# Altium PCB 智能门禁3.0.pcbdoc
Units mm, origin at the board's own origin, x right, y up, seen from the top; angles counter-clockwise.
Board outline 222.24 x 108 mm, 2 copper layers (Top Layer, Bottom Layer); 20 components, 31 nets, 107 pads, 14 vias.
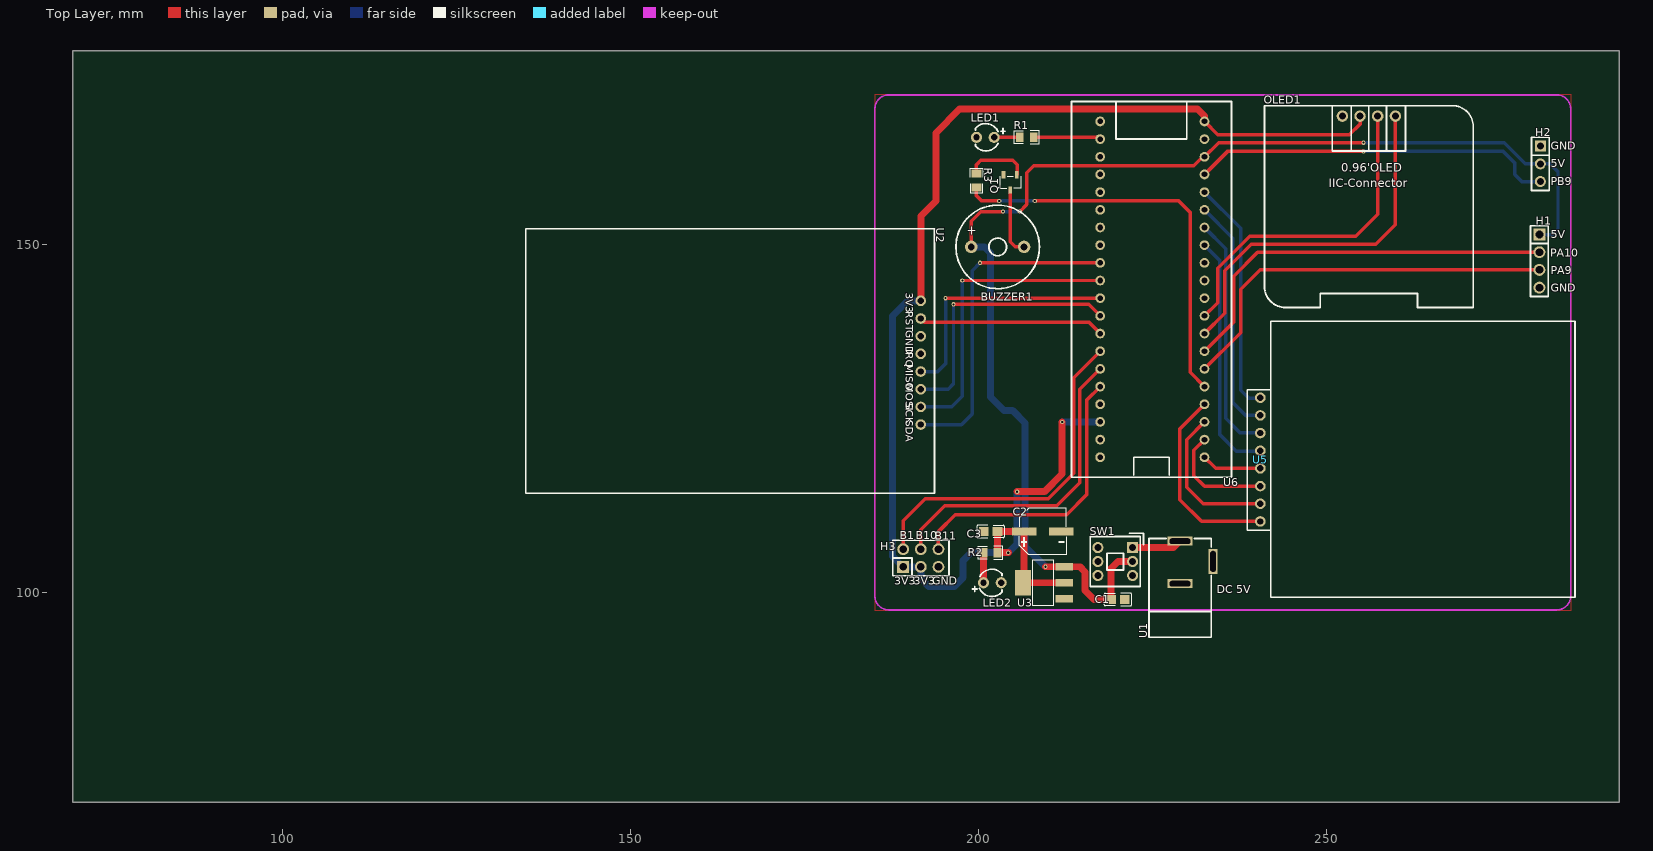
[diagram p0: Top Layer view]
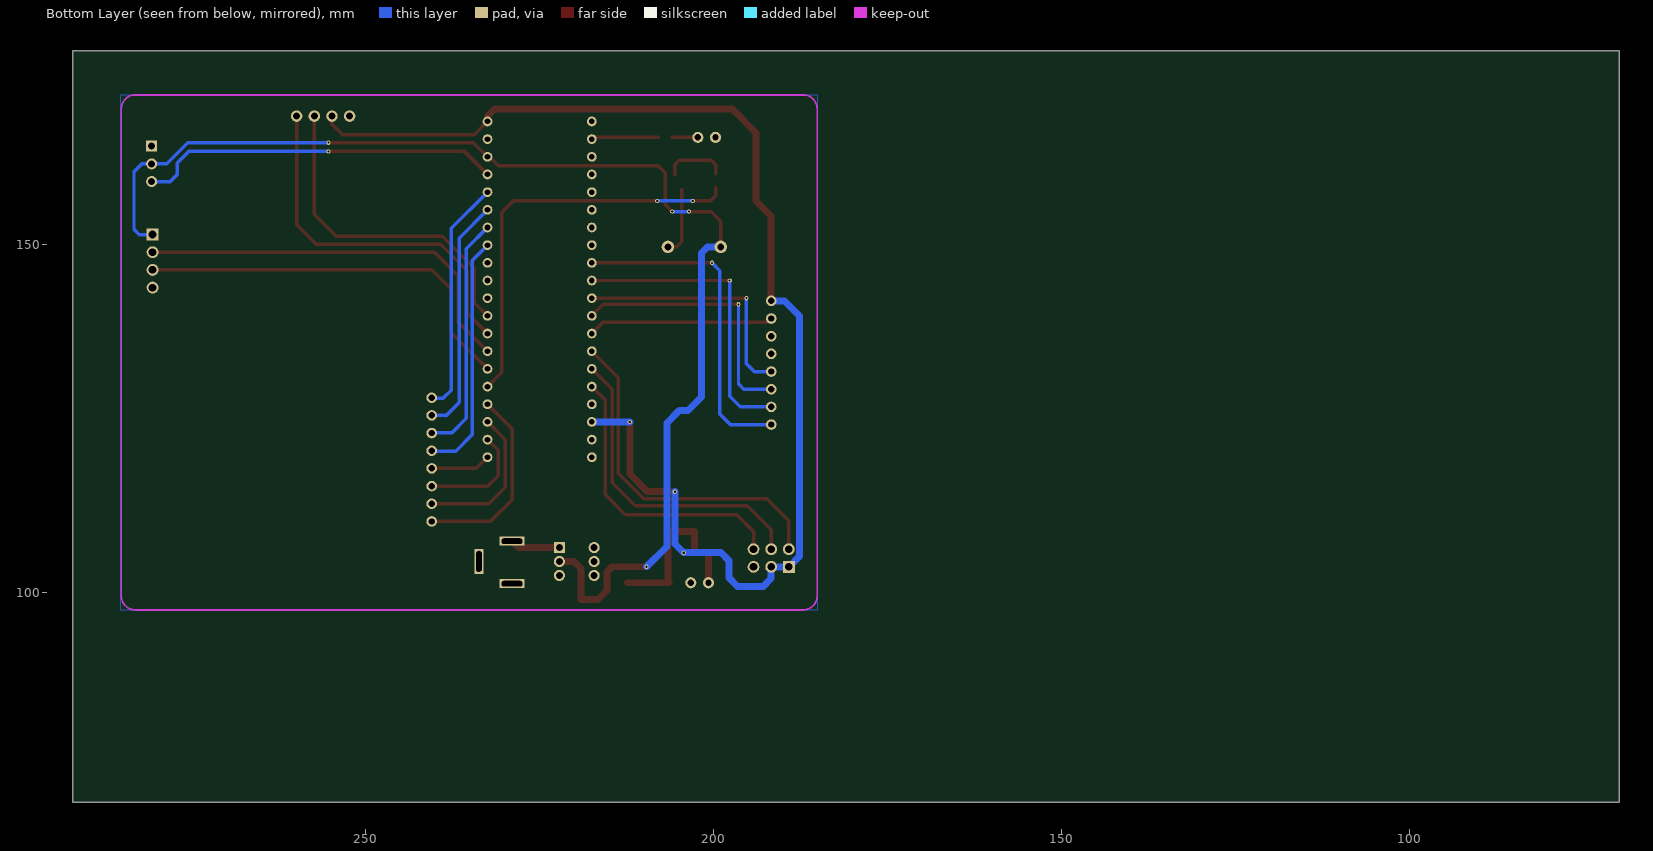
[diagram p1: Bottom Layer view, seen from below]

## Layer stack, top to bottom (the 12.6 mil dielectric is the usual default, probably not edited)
Top Layer: signal copper (thickness not stored)
Dielectric: dielectric 0.32, FR-4, Dk 4.8
Bottom Layer: signal copper (thickness not stored)

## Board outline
292.094,69.85 69.85,69.85 69.85,177.846 292.094,177.846

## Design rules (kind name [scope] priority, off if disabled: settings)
Clearance copperThickness1oz [All] p1: gap=0.178 ignorepadtopadclearanceinfootprint=FALSE except(0.102: Track-Track; 0.152: Track-SMDPad SMDPad-SMDPad Track-THPad SMDPad-THPad THPad-THPad Track-Via SMDPad-Via THPad-Via Via-Via Track-Fill SMDPad-Fill THPad-Fill Via-Fill Fill-Fill SMDPad-Region THPad-Region Via-Region Fill-Region Region-Region Track-Poly SMDPad-Poly THPad-Poly Via-Poly Fill-Poly Poly-Poly Track-Text SMDPad-Text THPad-Text Via-Text Fill-Text Region-Text Poly-Text Text-Text Track-Hole SMDPad-Hole THPad-Hole Via-Hole Fill-Hole Region-Hole Poly-Hole Text-Hole; 0.3: Track-Region Region-Poly Track-Sheet SMDPad-Sheet THPad-Sheet Via-Sheet Fill-Sheet Region-Sheet Poly-Sheet Text-Sheet Sheet-Hole)
Clearance copperThickness2oz [All] p1: gap=0.178 ignorepadtopadclearanceinfootprint=FALSE except(0.152: Track-SMDPad SMDPad-SMDPad Track-THPad SMDPad-THPad THPad-THPad Track-Via SMDPad-Via THPad-Via Via-Via Track-Fill SMDPad-Fill THPad-Fill Via-Fill Fill-Fill SMDPad-Region THPad-Region Via-Region Fill-Region Region-Region Track-Poly SMDPad-Poly THPad-Poly Via-Poly Fill-Poly Poly-Poly Track-Text SMDPad-Text THPad-Text Via-Text Fill-Text Region-Text Poly-Text Text-Text Track-Hole SMDPad-Hole THPad-Hole Via-Hole Fill-Hole Region-Hole Poly-Hole Text-Hole; 0.203: Track-Track; 0.3: Track-Region Region-Poly Track-Sheet SMDPad-Sheet THPad-Sheet Via-Sheet Fill-Sheet Region-Sheet Poly-Sheet Text-Sheet Sheet-Hole)
DiffPairsRouting differentialPair [All] p1: maxuncoupledlength=10 maxlimit=6 mostfreqgap=6 toplayer_minwidth=5 toplayer_prefwidth=10 toplayer_maxwidth=100 bottomlayer_minwidth=5 bottomlayer_prefwidth=10 bottomlayer_maxwidth=100
PasteMaskExpansion pasteMaskExpansion [All] p1:
PlaneConnect innerPlane [All] p1: planeconnectstyle=Relief reliefexpansion=0.508 reliefentries=4 reliefconductorwidth=0.254 reliefairgap=0.254
PolygonConnect copperRegion [All] p1: connectstyle=Relief reliefentries=4 reliefconductorwidth=10 polygonreliefangle="90 Angle" airgapwidth=10
RoutingVias viaSize [All] p1: viastyle="Through Hole" holewidth=12.0078 minholewidth=11.811 maxholewidth=248.0314 width=24.0158 minwidth=19.685 maxwidth=393.7008
SolderMaskExpansion solderMaskExpansion [All] p1: useseparateexpansions=TRUE expansion=2 expansionbottom=2
Width copperThickness1oz [All] p1: maxlimit=100 minlimit=5 preferedwidth=10
Width copperThickness2oz [All] p1: maxlimit=100 minlimit=8 preferedwidth=10

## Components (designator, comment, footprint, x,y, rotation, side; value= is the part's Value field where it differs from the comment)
BUZZER1 "TMB12A03" BUZ-TH_BD12.0-P7.60-D0.6-FD 202.771,149.652 r0 top
C1 "CC0805JRX7R7BB104" C0805 220.043,98.979 r0 top
C2 "RVT220UF16V67RV0015" CAP-SMD_BD6.3-L6.6-W6.6-FD 209.248,108.758 r0 top
C3 "CC0805JRX7R7BB104" C0805 201.755,108.758 r180 top
H1 "PZ254V-11-04P" HDR-TH_4P-P2.54-V-M 280.622,147.62 r270 top
H2 "PM254V-11-03-H85" HDR-TH_3P-P2.54-V-F 280.749,161.59 r270 top
H3 "PZ254V-12-6P" HDR-TH_6P-P2.54-V-M-R2-C3-S2.54 191.722,104.948 r0 top
LED1 "204-10SUGD/S400-A4-L" LED-TH_BD3.9-P2.54-RD 200.993,165.4 r0 top
LED2 "204-10SUGD/S400-A4-L" LED-TH_BD3.9-P2.54-RD 202.009,101.392 r180 top
OLED1 "0.96OLED模块_4P" 0.96OLED_4P 256.111,168.448 r0 top
Q1 "S8050 J3Y_C2146" SOT-23-3_L3.0-W1.7-P0.95-LS2.9-BR 204.568,158.936 r90 top
R1 "0805W8F1001T5E" R0805 206.946,165.416 r0 top
R2 "0805W8F1001T5E" R0805 201.755,105.71 r0 top
R3 "0805W8F1001T5E" R0805 199.723,159.177 r270 top
SW1 "XKB7070-Z" SW-TH_6P-L7.0-W7.0-P2.00 219.662,104.44 r0 top
U1 "ZX-DC-WC2.56.3" DC-TH_ZX-DC-WC2.56.3 231.346,104.313 r90 top
U2 "RC522" RC522 168.608,134.92 r270 top
U3 "AMS1117-3.3_C6186" SOT-223-3_L6.5-W3.4-P2.30-LS7.0-BR 209.375,101.392 r0 top
U5 "矩阵键盘" 矩阵键盘 242.014,138.984 r0 top
U6 "STM32F103C8T6" STM32F103C8T6 224.869,143.556 r180 top

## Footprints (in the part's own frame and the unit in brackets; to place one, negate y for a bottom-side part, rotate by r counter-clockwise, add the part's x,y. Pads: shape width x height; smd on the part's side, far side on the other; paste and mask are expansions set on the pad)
0.96OLED_4P [mm]
  round 1.65 hole 1 copper offset 0,0: 1(-3.81,-0.002) 2(-1.27,0.001) 3(1.27,0.001) 4(3.81,0.001)
  silkscreen extent -15,-27.5 15,1.5
BUZ-TH_BD12.0-P7.60-D0.6-FD [mm]
  round 1.8 hole 1: 1(-3.8,0) 2(3.8,0)
  silkscreen extent -6,-6 6,6
C0805 [mm]
  rect 1.41x1.35 smd: 1(-1,0) 2(1,0)
  silkscreen extent -1.96,-0.9 1.96,0.9
CAP-SMD_BD6.3-L6.6-W6.6-FD [mm]
  rect 3.5x1.2 smd: 1(-2.67,0) 2(2.67,0)
  silkscreen extent -3.38,-3.38 3.38,3.38
DC-TH_ZX-DC-WC2.56.3 [mm]
  rect 1.3x3.6 hole 0.8 slot 3 at 90 deg: 1(3.05,2.375) 2(-3.05,2.375)
  rect 3.6x1.3 hole 0.8 slot 3 at 0 deg: 3(0.15,-2.375)
  silkscreen extent -10.75,-2.12 3.45,6.82
HDR-TH_3P-P2.54-V-F [mil]
  rect 62x62 hole 40.16: 1(-100,0)
  round 62 hole 40.16: 2(0,0) 3(100,0)
  silkscreen extent -150,-50 150,50
HDR-TH_4P-P2.54-V-M [mm]
  rect 1.7x1.7 hole 1.1: 1(-3.81,0)
  round 1.7 hole 1.1: 2(-1.27,0) 3(1.27,0) 4(3.81,0)
  silkscreen extent -5.08,-1.27 5.08,1.27
HDR-TH_6P-P2.54-V-M-R2-C3-S2.54 [mm]
  rect 1.7x1.7 hole 1.1: 1(-2.54,-1.27)
  round 1.7 hole 1.1: 2(-2.54,1.27) 3(0,-1.27) 4(0,1.27) 5(2.54,-1.27) 6(2.54,1.27)
  silkscreen extent -4.04,-2.54 4.04,2.54
LED-TH_BD3.9-P2.54-RD [mm]
  round 1.6 hole 0.9 copper offset 0,0: 1(-1.27,0) 2(1.27,0)
  silkscreen extent -1.42,-1.94 2.86,1.97
R0805 [mm]
  rect 1.133x1.377 smd: 1(-1,0) 2(1,0)
  silkscreen extent -1.76,-0.92 1.76,0.92
RC522 [mil]
  round 60 hole 36: 1(425,910) 2(325,910) 3(225,910) 4(125,910) 5(25,910) 6(-75,910) 7(-175,910) 8(-275,910)
  silkscreen extent -683,-1326 814,987
SOT-23-3_L3.0-W1.7-P0.95-LS2.9-BR [mm]
  rect 1.037x0.532 smd: 1(1.101,-0.95) 2(1.101,0.95) 3(-1.101,0)
  silkscreen extent -0.86,-1.53 0.86,1.53
SOT-223-3_L6.5-W3.4-P2.30-LS7.0-BR [mm]
  rect 2.5x1.1 smd: 1(2.97,-2.3) 2(2.97,0) 3(2.97,2.3)
  rect 2.34x3.6 smd: 4(-2.97,0)
  silkscreen extent -1.57,-3.33 1.37,3.33
STM32F103C8T6 [mm]
  round 1.4 hole 0.8: 1(-7.62,24.13) 2(-7.62,21.59) 3(-7.62,19.05) 4(-7.62,16.51) 5(-7.62,13.97) 6(-7.62,11.43) 7(-7.62,8.89) 8(-7.62,6.35) 9(-7.62,3.81) 10(-7.62,1.27) 11(-7.62,-1.27) 12(-7.62,-3.81) 13(-7.62,-6.35) 14(-7.62,-8.89) 15(-7.62,-11.43) 16(-7.62,-13.97) 17(-7.62,-16.51) 18(-7.62,-19.05) 19(-7.62,-21.59) 20(-7.62,-24.13) 21(7.366,-24.13) 22(7.366,-21.59) 23(7.366,-19.05) 24(7.366,-16.51) 25(7.366,-13.97) 26(7.366,-11.43) 27(7.366,-8.89) 28(7.366,-6.35) 29(7.366,-3.81) 30(7.366,-1.27) 31(7.366,1.27) 32(7.366,3.81) 33(7.366,6.35) 34(7.366,8.89) 35(7.366,11.43) 36(7.366,13.97) 37(7.366,16.51) 38(7.366,19.05) 39(7.366,21.59) 40(7.366,24.13)
  silkscreen extent -11.5,-27 11.5,27
SW-TH_6P-L7.0-W7.0-P2.00 [mm]
  rect 1.6x1.6 hole 1: 1(2.5,2)
  round 1.6 hole 1: 2(2.5,0) 3(2.5,-2) 4(-2.5,2) 5(-2.5,0) 6(-2.5,-2)
  silkscreen extent -3.6,-3.6 4.06,4.06
矩阵键盘 [mil]
  round 60 hole 36: 1(-59.06,-433.07) 2(-59.06,-533.07) 3(-59.06,-633.07) 4(-59.06,-733.07) 5(-59.06,-833.07) 6(-59.06,-933.07) 7(-59.06,-1033.07) 8(-59.06,-1133.07)
  silkscreen extent -133,-1561 1722,0

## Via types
v1: diameter 0.61, hole 0.305, Top Layer to Bottom Layer, 14 vias

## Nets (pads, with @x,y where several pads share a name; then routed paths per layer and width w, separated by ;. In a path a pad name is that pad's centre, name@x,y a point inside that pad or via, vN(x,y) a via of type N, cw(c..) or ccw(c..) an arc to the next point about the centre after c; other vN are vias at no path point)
3V3: C2.1 C3.1 H3.1 H3.3 OLED1.2 R2.2 U2.8 U3.2 U3.4 U6.20 U6.38 | length 205
  Top Layer w0.5: U6.20 234.394,165.781 253.317,165.781 254.841,167.305 OLED1.2@254.841,168.449
  Top Layer w1: U2.8 191.722,154.097 193.881,156.256 193.881,166.035 197.31,169.464 231.489,169.464 232.489,168.464 U6.20 ; v1(204.295,105.71) R2.2 C3.1 C2.1 206.578,101.565 U3.4 U3.2 ; v1(205.565,114.473) 209.502,114.473 212.042,117.013 v1(212.042,124.506)
  Bottom Layer w1: U2.8 189.817,141.905 187.658,139.746 187.658,105.202 H3.1 H3.3 191.722,102.027 192.865,100.884 196.548,100.884 197.818,102.154 197.818,104.567 198.961,105.71 v1(204.295,105.71) 205.565,106.98 v1(205.565,114.473) ; v1(212.042,124.506) U6.38
$1N396: SW1.1 U1.1 | length 7.2
  Top Layer w1: SW1.1 228.048,106.44 U1.1
$1N399: LED2.2 R2.1 | length 4.3
  Top Layer w1: LED2.2 200.755,101.408 R2.1
$1N653: LED1.2 R1.1 | length 3.7
  Top Layer w0.5: LED1.2 202.279,165.416 R1.1
$1N7362: BUZZER1.2 Q1.3 | length 9.8
  Top Layer w0.5: Q1.3 204.568,150.395 205.311,149.652 BUZZER1.2
$1N7364: Q1.1 R3.1 | length 9.1
  Top Layer w0.5: R3.1 199.723,161.463 200.358,162.098 204.93,162.098 205.565,161.463 205.565,160.084 Q1.1
+5V: BUZZER1.1 C1.1 H1.1 H2.2 SW1.2 U3.3 U6.18 | length 181.5
  Top Layer w0.5: BUZZER1.1 198.971,153.345 200.358,154.732 v1(203.533,154.732) ; v1(205.946,154.732) 206.962,155.748 206.962,160.32 207.978,161.336 230.965,161.336 232.235,162.606 U6.18 234.521,164.638 v1(255.349,164.638)
  Top Layer w1: v1(209.629,103.692) U3.3 214.568,103.692 215.344,102.916 215.344,100.249 216.598,98.995 C1.1@219.027,98.995 ; C1.1 C1.1@219.027,98.995 ; SW1.2 220.043,104.44 219.027,103.424 C1.1@219.027,98.995
  Bottom Layer w0.5: v1(203.533,154.732) v1(205.946,154.732) ; v1(255.349,164.638) 275.542,164.638 278.59,161.59 H2.2 282.146,161.59 283.289,160.447 283.289,152.192 282.527,151.43 H1.1
  Bottom Layer w1: BUZZER1.1 200.866,149.652 201.755,148.763 201.755,128.062 203.66,126.157 204.93,126.157 206.708,124.379 206.708,106.613 v1(209.629,103.692)
GND: C1.2 C2.2 C3.2 H1.4 H2.1 H3.5 LED1.1 LED2.1 OLED1.1 Q1.2 U1.2 U1.3 U2.6 U3.1 U6.19 U6.39 U6.40
PA4: U2.1 U6.29 | length 47.5
  Top Layer w0.5: v1(200.231,147.366) U6.29
  Bottom Layer w0.5: U2.1 197.564,124.125 199.088,125.649 199.088,146.223 v1(200.231,147.366)
PA5: 
PA6: U2.4 U6.31 | length 35.7
  Top Layer w0.5: v1(195.278,142.286) U6.31
  Bottom Layer w0.5: U2.4 194.135,131.745 195.278,132.888 v1(195.278,142.286)
PA7: U2.3 U6.32 | length 38.2
  Top Layer w0.5: v1(196.421,141.397) 215.852,141.397 U6.32
  Bottom Layer w0.5: U2.3 195.659,129.205 196.421,129.967 v1(196.421,141.397)
PA8: R3.2 U6.5 | length 58.8
  Top Layer w0.5: R3.2 199.723,157.018 200.485,156.256 v1(202.991,156.256) ; v1(208.105,156.256) 228.806,156.256 230.457,154.605 230.457,131.618 U6.5
  Bottom Layer w0.5: v1(202.991,156.256) v1(208.105,156.256)
PA9: H1.3 U6.6 | length 57.7
  Top Layer w0.5: U6.6 237.696,137.333 237.696,143.556 240.49,146.35 H1.3
PA10: H1.2 U6.7 | length 57.9
  Top Layer w0.5: U6.7 236.68,138.857 236.68,145.461 240.109,148.89 H1.2
PA11: OLED1.4 U6.8 | length 53.1
  Top Layer w0.5: U6.8 235.41,140.127 235.41,146.223 239.22,150.033 257.127,150.033 259.921,152.827 OLED1.4@259.921,168.449
PA12: OLED1.3 U6.9 | length 47.9
  Top Layer w0.5: U6.9 234.394,141.651 234.394,146.604 238.966,151.176 254.206,151.176 257.381,154.351 OLED1.3@257.381,168.449
PB0: U2.7 U6.33 | length 26.7
  Top Layer w0.5: U2.7 192.23,138.857 215.852,138.857 U6.33
PB1: H3.2 U6.34 | length 50.5
  Top Layer w0.5: H3.2 189.182,110.282 192.357,113.457 210.01,113.457 213.693,117.14 213.693,130.856 U6.34
PB5: U5.4 U6.13 | length 35
  Bottom Layer w0.5: U6.13 234.648,147.747 234.648,122.728 237.061,120.315 240.465,120.315 U5.4
PB6: U5.3 U6.14 | length 34.5
  Bottom Layer w0.5: U6.14 235.537,149.398 235.537,125.014 237.569,122.982 240.436,122.982 U5.3
PB7: U5.2 U6.15 | length 34.1
  Bottom Layer w0.5: U6.15 236.553,150.922 236.553,127.3 238.458,125.395 238.507,125.444 U5.2
PB8: U5.1 U6.16 | length 33.9
  Bottom Layer w0.5: U6.16 237.696,152.319 237.696,129.078 238.839,127.935 240.465,127.935 U5.1
PB9: H2.3 U6.17 | length 52.4
  Top Layer w0.5: U6.17 235.791,163.368 v1(255.349,163.368)
  Bottom Layer w0.5: v1(255.349,163.368) 275.415,163.368 277.066,161.717 277.066,160.066 278.082,159.05 H2.3
PB10: H3.4 U6.35 | length 46
  Top Layer w0.5: H3.4 191.722,109.012 195.151,112.441 211.28,112.441 214.582,115.743 214.582,129.205 U6.35
PB11: H3.6 U6.36 | length 42.4
  Top Layer w0.5: H3.6 194.262,108.758 196.675,111.171 212.677,111.171 215.598,114.092 215.598,127.681 U6.36
PB12: U5.5 U6.1 | length 8.7
  Top Layer w0.5: U6.1 234.091,117.824 U5.5
PB13: U5.6 U6.2 | length 16
  Top Layer w0.5: U6.2 230.965,120.442 230.965,116.759 232.489,115.235 240.465,115.235 U5.6
PB14: U5.7 U6.3 | length 22
  Top Layer w0.5: U6.3 229.949,121.966 229.949,115.108 232.313,112.744 U5.7
PB15: U5.8 U6.4 | length 28.1
  Top Layer w0.5: U6.4 228.933,123.49 228.933,113.33 232.059,110.204 U5.8
PC13: R1.2 U6.22 | length 9.7
  Top Layer w0.5: R1.2 217.233,165.416 U6.22
pads on no net: SW1.3 SW1.4 SW1.5 SW1.6 U2.2 U2.5 U6.10 U6.11 U6.12 U6.21 U6.23 U6.24 U6.25 U6.26 U6.27 U6.28 U6.30 U6.37
copper on no net: | length 43
  Top Layer w0.5: v1(197.691,144.826) 217.503,144.826
  Bottom Layer w0.5: 191.722,126.665 196.167,126.665 197.691,128.189 v1(197.691,144.826)

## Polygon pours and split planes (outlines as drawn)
GND on Top Layer (solid, remove dead copper): 185.118,97.455 285.194,97.455 285.194,171.496 185.118,171.496
GND on Bottom Layer (solid, remove dead copper, pour order 4): 185.118,97.455 285.194,97.455 285.194,171.496 185.118,171.496

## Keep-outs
Board Outline Layer:
  lines w0.254: 185.118,99.496 ccw(c187.118,99.496) 187.118,97.496 283.118,97.496 ccw(c283.118,99.496) 285.118,99.496 285.118,169.496 ccw(c283.118,169.496) 283.118,171.496 187.118,171.496 ccw(c187.118,169.496) 185.118,169.496 185.118,99.496

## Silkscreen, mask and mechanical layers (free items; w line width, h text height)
Top Silkscreen Layer:
  text "GND" at 282.273,163.622 h1.14
  text "5V" at 282.273,161.082 h1.14
  text "PB9" at 282.273,158.542 h1.14
  text "5V" at 282.273,150.922 h1.14
  text "PA10" at 282.146,148.255 h1.14
  text "PA9" at 282.273,145.715 h1.14
  text "GND" at 282.273,143.175 h1.14
  text "B1" at 188.674,107.615 h1.14
  text "B10" at 190.96,107.615 h1.14
  text "B11" at 193.754,107.584 h1.14
  text "3V3" at 187.912,101.138 h1.14
  text "3V3" at 190.706,101.138 h1.14
  text "GND" at 193.373,101.138 h1.14
  text "DC 5V" at 234.267,99.868 h1.14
